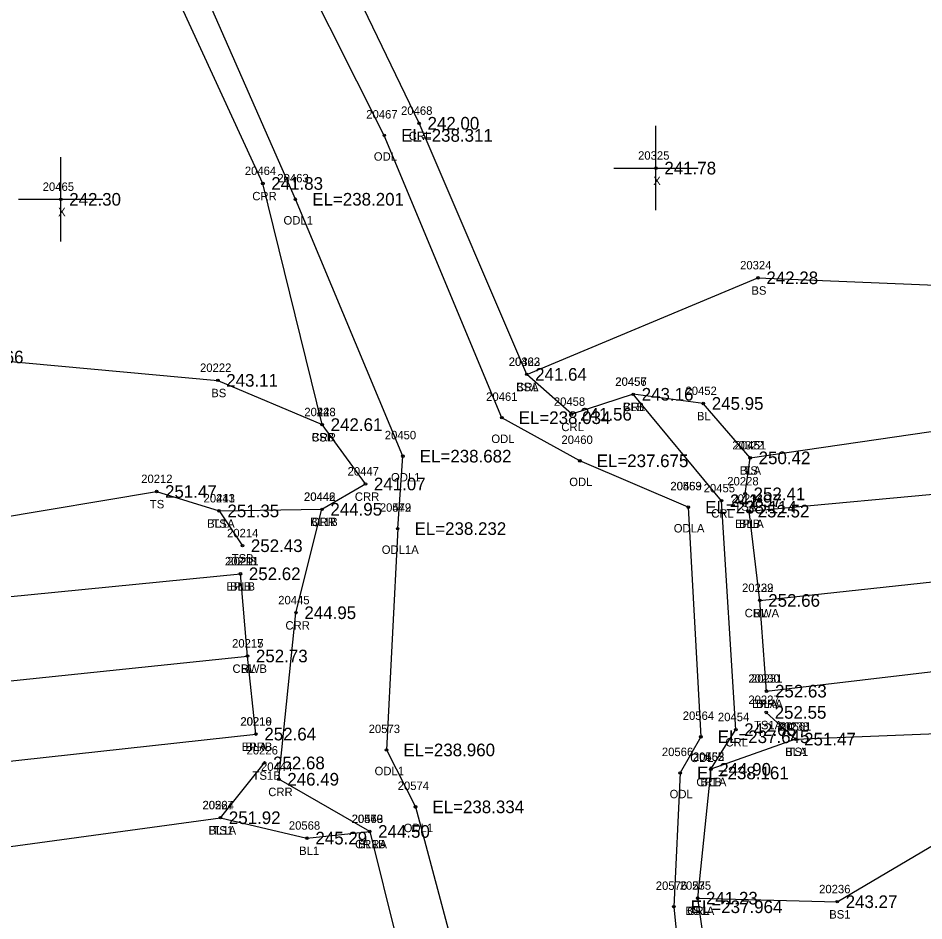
# Model space of a CAD drawing. Extents: x 2275563 to 2277161, y 1075719 to 1076412.
# Drawn here: x 2276292.5 to 2276399.9, y 1076035.8 to 1076142.9 of the extents above; entities that cross this region are included whole.
import ezdxf

# ---------------------------------------------------------------- set-up
doc = ezdxf.new("R2010")
doc.units = 0
for name, color, linetype in [('RD_DTM_BkLn1', 7, 'Continuous'), ('RD_DTM_BkLn2', 7, 'Continuous'), ('RD_DTM_BkLn_txCode', 7, 'Continuous'), ('RD_EX_H2O', 7, 'Continuous'), ('RD_EX_H2O_txCode', 7, 'Continuous'), ('RD_EX_Misc', 7, 'Continuous'), ('RD_EX_Misc_txCode', 7, 'Continuous'), ('RD_EX_Road', 7, 'Continuous'), ('RD_EX_Road_txCode', 7, 'Continuous'), ('RD_EX_TX_H2O_ELEV', 7, 'Continuous'), ('RD_EX_TX_Misc_ELEV', 7, 'Continuous'), ('RD_EX_TX_Road_ELEV', 7, 'Continuous'), ('RD_HC_Survey_ELEV', 7, 'Continuous'), ('RD_HC_Survey_txCode', 7, 'Continuous'), ('RD_SMD_Locator', 7, 'Continuous')]:
    doc.layers.add(name, color=color, linetype=linetype)

msp = doc.modelspace()

# ---------------------------------------------------------------- linework, layer by layer
at = {"layer": 'RD_DTM_BkLn1'}
for p, q in [((2276316.33, 1076084.42), (2276328.54, 1076084.61)), ((2276384.72, 1076057.35), (2276374.66, 1076053.77))]:
    msp.add_line(p, q, dxfattribs=at)
for points in [[(2276380.47, 1076073.8), (2276432.36, 1076079.4), (2276487.41, 1076086.42), (2276535.62, 1076093.32), (2276578.15, 1076099.97), (2276622.03, 1076107.93), (2276668.51, 1076117.27), (2276714.2, 1076127.81), (2276762.94, 1076140.11), (2276806.88, 1076151.96), (2276854.94, 1076166.29), (2276899.73, 1076180.7), (2276952.88, 1076198.57), (2277000.46, 1076214.72), (2277057.1, 1076234.01), (2277134.93, 1076261.07)], [(2276379.33, 1076090.71), (2276373.77, 1076097.16), (2276365.46, 1076098.25)], [(2276381.27, 1076063.04), (2276380.47, 1076073.8), (2276379.21, 1076084.39)], [(2276320.71, 1076057.95), (2276319.71, 1076067.21), (2276318.87, 1076076.96)], [(2275581.11, 1075960.98), (2275628.56, 1075975.85), (2275676.42, 1075988.42), (2275723.3, 1075998.64), (2275773.11, 1076007.87), (2275820.75, 1076014.85), (2275866.6, 1076020.4), (2275966.91, 1076031.19), (2276055.16, 1076040.4), (2276149.88, 1076050.18), (2276235.38, 1076058.41), (2276319.71, 1076067.21)], [(2276316.5, 1076048.03), (2276326.76, 1076045.61), (2276334.2, 1076046.4)]]:
    msp.add_lwpolyline(points, dxfattribs=at)
at = {"layer": 'RD_DTM_BkLn2'}
for points in [[(2276352.82, 1076100.61), (2276380.25, 1076112.06), (2276428.17, 1076110.1), (2276479.59, 1076123.58), (2276530.51, 1076128.25), (2276572.26, 1076136.92), (2276616.95, 1076145.31), (2276657.47, 1076152.34)], [(2276378.73, 1076086.44), (2276379.33, 1076090.71), (2276430.69, 1076098.18), (2276485.24, 1076104.54), (2276534.86, 1076111.23), (2276576.67, 1076117.6), (2276619.01, 1076127.99), (2276664.32, 1076137.81), (2276675.37, 1076140.15)], [(2275996.63, 1076057.66), (2276055.36, 1076067.63), (2276157.86, 1076085.08), (2276161.29, 1076085.91), (2276230.76, 1076096.53), (2276259.06, 1076089.7), (2276286.01, 1076102.67), (2276316.19, 1076099.9), (2276328.57, 1076094.65)], [(2276381.23, 1076060.52), (2276384.72, 1076057.35), (2276432.14, 1076059.24), (2276489.29, 1076068.7), (2276538.36, 1076076.43), (2276580.68, 1076083.56), (2276626.16, 1076090.05), (2276659.02, 1076095.85)], [(2276005.18, 1076050.59), (2276054, 1076055.99), (2276147.58, 1076070.47), (2276233.91, 1076079.18), (2276270.23, 1076080.23), (2276308.93, 1076086.72), (2276316.33, 1076084.42), (2276319.11, 1076080.29)], [(2276373.09, 1076038.49), (2276389.65, 1076038.07), (2276402.95, 1076045.94), (2276434.46, 1076042.78), (2276488.57, 1076051.06), (2276535.54, 1076055.99), (2276577.32, 1076064.99)], [(2276110, 1076025.4), (2276151.71, 1076032.16), (2276238.86, 1076037.41), (2276316.5, 1076048.03), (2276321.74, 1076054.53)]]:
    msp.add_lwpolyline(points, dxfattribs=at)
at = {"layer": 'RD_EX_H2O'}
for points in [[(2276371.99, 1076084.86), (2276359.12, 1076090.36), (2276349.87, 1076095.47), (2276335.93, 1076128.95), (2276310.08, 1076180.39), (2276310.66, 1076200.13), (2276321.83, 1076198.34), (2276333.62, 1076185.76), (2276354.83, 1076182.14), (2276364.71, 1076198.02), (2276372.09, 1076234.22), (2276380.37, 1076246.34), (2276391.97, 1076247.22), (2276452.13, 1076223.15), (2276471.36, 1076222.63), (2276478.94, 1076232.98), (2276472.33, 1076282.9), (2276448.49, 1076309.21), (2276451.67, 1076322.37), (2276482.4, 1076359.1), (2276495.19, 1076406.32)], [(2276374.66, 1076053.77), (2276377.62, 1076058.48), (2276375.93, 1076085.62), (2276365.46, 1076098.25), (2276358.16, 1076095.88), (2276352.82, 1076100.61), (2276340.06, 1076130.39), (2276314.72, 1076182.94), (2276314.31, 1076195.95), (2276321.34, 1076195.98), (2276333.33, 1076184.02), (2276355.21, 1076176.64), (2276375.26, 1076196.07), (2276380, 1076232.36), (2276383.62, 1076239.24), (2276390.64, 1076244.46), (2276451.84, 1076220.12), (2276472.79, 1076219.91), (2276480.77, 1076232.08), (2276477.11, 1076285.34), (2276453.42, 1076310.35), (2276458.35, 1076317.97), (2276489.24, 1076360.6), (2276498.15, 1076406.79)], [(2276337.52, 1076082.32), (2276338.14, 1076090.91), (2276325.39, 1076121.38), (2276301.23, 1076176.38), (2276301.47, 1076212.03), (2276303.94, 1076212.33), (2276322.96, 1076208.7), (2276333.72, 1076197.42), (2276353.59, 1076194.54), (2276358.22, 1076208.33), (2276360.94, 1076233.4), (2276370.36, 1076250.64), (2276386.18, 1076258.85), (2276454.86, 1076231.51), (2276469.16, 1076242), (2276461.94, 1076274.88), (2276441.6, 1076298.83), (2276443.32, 1076327.87), (2276470.76, 1076362.4), (2276481.62, 1076405.55)], [(2276334.2, 1076046.4), (2276323.43, 1076052.59), (2276325.46, 1076072.34), (2276328.54, 1076084.61), (2276333.7, 1076087.61), (2276328.57, 1076094.65), (2276321.53, 1076123.25), (2276297.42, 1076175.68), (2276298.22, 1076215.44)], [(2276371.99, 1076084.86), (2276373.47, 1076057.63), (2276371.02, 1076053.34), (2276370.27, 1076037.47), (2276373.78, 1076001.78), (2276377.12, 1075939.07), (2276387.12, 1075924.65), (2276409.24, 1075914.33), (2276440.66, 1075900.23), (2276458.72, 1075909.41), (2276468.75, 1075909.62), (2276481.14, 1075898.88), (2276470.97, 1075847.84), (2276468.69, 1075801.1), (2276495.71, 1075755.91), (2276526.48, 1075747.54)], [(2276337.52, 1076082.32), (2276336.19, 1076056.07), (2276339.64, 1076049.32), (2276347.49, 1076019.86), (2276346.94, 1075980.53), (2276334.04, 1075961.68), (2276358.91, 1075924.16), (2276390.72, 1075889.91), (2276404.64, 1075906.32), (2276409.35, 1075902.87), (2276425.82, 1075890.52), (2276463.29, 1075896.33), (2276470.94, 1075887.1), (2276454.43, 1075853.34), (2276454.95, 1075812.59), (2276477.48, 1075753.76), (2276516.05, 1075739.78)], [(2276374.66, 1076053.77), (2276373.09, 1076038.49), (2276378.35, 1076001.85), (2276379.41, 1075939.56), (2276393.18, 1075928.69), (2276410.52, 1075916.05), (2276439.66, 1075905.97), (2276458.4, 1075912.38), (2276470.74, 1075911.86), (2276484.27, 1075900.43), (2276472.97, 1075846.67), (2276473.8, 1075804.25), (2276499.15, 1075757.95), (2276529.69, 1075749.92)], [(2276334.2, 1076046.4), (2276337.42, 1076033.52), (2276345.85, 1076017.42), (2276339.02, 1075984.54), (2276329.97, 1075967.39)]]:
    msp.add_lwpolyline(points, dxfattribs=at)
at = {"layer": 'RD_EX_Misc'}
for p, q in [((2276368.15, 1076120.07), (2276368.15, 1076130.07)), ((2276297.57, 1076116.37), (2276297.57, 1076126.37)), ((2276363.15, 1076125.07), (2276373.15, 1076125.07)), ((2276292.57, 1076121.37), (2276302.57, 1076121.37))]:
    msp.add_line(p, q, dxfattribs=at)
at = {"layer": 'RD_EX_Road'}
for points in [[(2276379.21, 1076084.39), (2276432.25, 1076089.28), (2276486.22, 1076095.98), (2276535.61, 1076103.32), (2276577.16, 1076110.11), (2276620.86, 1076117.78), (2276666.21, 1076126.9), (2276712, 1076137.22), (2276761.13, 1076149.72), (2276804.56, 1076161.71), (2276851.24, 1076175.53), (2276896.93, 1076190.53), (2276950.19, 1076208.22), (2276997.45, 1076224.3), (2277053.81, 1076243.77), (2277132.14, 1076270.77)], [(2276381.27, 1076063.04), (2276433.15, 1076069.16), (2276488.59, 1076076.23), (2276537.45, 1076083.34), (2276579.64, 1076090.09), (2276624.07, 1076098.24), (2276670.54, 1076107.46), (2276716.67, 1076118.09), (2276765.18, 1076130.28), (2276809.58, 1076142.25), (2276856.93, 1076156.58), (2276903.53, 1076171.63), (2276957.27, 1076189.46), (2277005.85, 1076206.01), (2277060.98, 1076225.07), (2277139.5, 1076252.36)], [(2275577.73, 1075970.55), (2275625.95, 1075985.49), (2275674.01, 1075998.04), (2275722.5, 1076008.98), (2275771.65, 1076017.82), (2275820.48, 1076025.1), (2275865.7, 1076030.61), (2275949.17, 1076039.36), (2275965.19, 1076041.07), (2276054.28, 1076050.49), (2276149.42, 1076060.39), (2276235.13, 1076068.68), (2276318.87, 1076076.96)], [(2275583.24, 1075951.04), (2275629.66, 1075965.93), (2275678.06, 1075978.68), (2275725.56, 1075989.06), (2275775.66, 1075998.23), (2275820.79, 1076005.15), (2275867.87, 1076010.76), (2275970.82, 1076021.78), (2276056.64, 1076030.61), (2276150.8, 1076040.39), (2276237.04, 1076048.76), (2276320.71, 1076057.95)]]:
    msp.add_lwpolyline(points, dxfattribs=at)
at = {"layer": 'RD_SMD_Locator'}
for centre in [(2276340.06, 1076130.39), (2276335.93, 1076128.95), (2276368.15, 1076125.07), (2276321.53, 1076123.25), (2276297.57, 1076121.37), (2276325.39, 1076121.38), (2276380.25, 1076112.06), (2276316.19, 1076099.9), (2276352.82, 1076100.61), (2276352.82, 1076100.61), (2276365.46, 1076098.25), (2276365.46, 1076098.25), (2276373.77, 1076097.16), (2276349.87, 1076095.47), (2276358.16, 1076095.88), (2276328.57, 1076094.65), (2276328.57, 1076094.65), (2276338.14, 1076090.91), (2276359.12, 1076090.36), (2276379.33, 1076090.71), (2276379.33, 1076090.71), (2276308.93, 1076086.72), (2276333.7, 1076087.61), (2276375.93, 1076085.62), (2276378.73, 1076086.44), (2276328.54, 1076084.61), (2276328.54, 1076084.61), (2276371.99, 1076084.86), (2276371.99, 1076084.86), (2276316.33, 1076084.42), (2276316.33, 1076084.42), (2276379.21, 1076084.39), (2276379.21, 1076084.39), (2276337.52, 1076082.32), (2276337.52, 1076082.32), (2276319.11, 1076080.29), (2276318.87, 1076076.96), (2276318.87, 1076076.96), (2276380.47, 1076073.8), (2276380.47, 1076073.8), (2276325.46, 1076072.34), (2276319.71, 1076067.21), (2276319.71, 1076067.21), (2276381.27, 1076063.04), (2276381.27, 1076063.04), (2276381.23, 1076060.52), (2276320.71, 1076057.95), (2276320.71, 1076057.95), (2276377.62, 1076058.48), (2276373.47, 1076057.63), (2276384.72, 1076057.35), (2276384.72, 1076057.35), (2276336.19, 1076056.07), (2276321.74, 1076054.53), (2276374.66, 1076053.77), (2276374.66, 1076053.77), (2276374.66, 1076053.77), (2276323.43, 1076052.59), (2276371.02, 1076053.34), (2276339.64, 1076049.32), (2276316.5, 1076048.03), (2276316.5, 1076048.03), (2276334.2, 1076046.4), (2276334.2, 1076046.4), (2276334.2, 1076046.4), (2276326.76, 1076045.61), (2276373.09, 1076038.49), (2276373.09, 1076038.49), (2276370.27, 1076037.47), (2276389.65, 1076038.07)]:
    msp.add_circle(centre, 0.15, dxfattribs=at)

# ---------------------------------------------------------------- texts
at = {"layer": 'RD_DTM_BkLn_txCode'}
for s, p in [('20324', (2276378.13, 1076113.06)), ('BS', (2276379.47, 1076110.06)), ('20222', (2276314.08, 1076100.9)), ('20323', (2276350.7, 1076101.61)), ('20457', (2276363.34, 1076099.25)), ('BS', (2276315.41, 1076097.9)), ('BSA', (2276351.55, 1076098.61)), ('20452', (2276371.65, 1076098.16)), ('20223', (2276326.45, 1076095.65)), ('BLB', (2276364.23, 1076096.25)), ('BL', (2276373.01, 1076095.16)), ('BSB', (2276327.31, 1076092.65)), ('20322', (2276377.21, 1076091.71)), ('20451', (2276377.49, 1076091.71)), ('BLA', (2276378.09, 1076088.71)), ('TS', (2276378.53, 1076088.71)), ('20212', (2276307.1, 1076087.72)), ('20228', (2276376.61, 1076087.44)), ('20213', (2276314.5, 1076085.42)), ('20441', (2276314.5, 1076085.42)), ('20442', (2276326.42, 1076085.61)), ('20233', (2276377.1, 1076085.39)), ('TS', (2276308.13, 1076084.72)), ('TSA', (2276377.45, 1076084.44)), ('BL1B', (2276327.14, 1076082.61)), ('BL1A', (2276314.92, 1076082.42)), ('TS', (2276315.54, 1076082.42)), ('BLB', (2276377.99, 1076082.39)), ('20214', (2276317.28, 1076081.29)), ('TSB', (2276317.84, 1076078.29)), ('20218', (2276317.03, 1076077.96)), ('BLB', (2276317.64, 1076074.96)), ('20232', (2276378.36, 1076074.8)), ('BL', (2276379.72, 1076071.8)), ('20217', (2276317.88, 1076068.21)), ('BL', (2276318.96, 1076065.21)), ('20231', (2276379.43, 1076064.04)), ('20227', (2276379.11, 1076061.52)), ('BLA', (2276380.02, 1076061.04)), ('20216', (2276318.85, 1076058.95)), ('TS1A', (2276379.78, 1076058.52)), ('20238', (2276382.6, 1076058.35)), ('20561', (2276382.86, 1076058.35)), ('BLA', (2276319.47, 1076055.95)), ('20226', (2276319.6, 1076055.53)), ('20562', (2276372.52, 1076054.77)), ('BLA', (2276383.48, 1076055.35)), ('TS1', (2276383.76, 1076055.35)), ('TS1B', (2276320.31, 1076052.53)), ('BLB', (2276373.43, 1076051.77)), ('20567', (2276314.36, 1076049.03)), ('20224', (2276314.38, 1076049.03)), ('20569', (2276332.06, 1076047.4)), ('20568', (2276324.61, 1076046.61)), ('BL1A', (2276315.09, 1076046.03)), ('TS1', (2276315.54, 1076046.03)), ('BL1B', (2276332.81, 1076044.4)), ('BL1', (2276325.83, 1076043.61)), ('20235', (2276370.97, 1076039.49)), ('20236', (2276387.5, 1076039.07)), ('BS1A', (2276371.65, 1076036.49)), ('BS1', (2276388.7, 1076036.07))]:
    msp.add_text(s, height=1, dxfattribs=at).set_placement(p)
at = {"layer": 'RD_EX_H2O_txCode'}
for s, p in [('20467', (2276333.79, 1076130.95)), ('20468', (2276337.92, 1076131.39)), ('CRL', (2276338.83, 1076128.39)), ('ODL', (2276334.69, 1076125.95)), ('20464', (2276319.39, 1076124.25)), ('20463', (2276323.25, 1076123.38)), ('CRR', (2276320.28, 1076121.25)), ('ODL1', (2276323.98, 1076118.38)), ('20462', (2276350.68, 1076101.61)), ('20456', (2276363.32, 1076099.25)), ('CRL', (2276351.59, 1076098.61)), ('20461', (2276348.01, 1076097.47)), ('20458', (2276356.04, 1076096.88)), ('20448', (2276326.45, 1076095.65)), ('CRL', (2276364.23, 1076096.25)), ('CRL', (2276356.93, 1076093.88)), ('CRR', (2276327.31, 1076092.65)), ('20450', (2276335.99, 1076092.91)), ('ODL', (2276348.63, 1076092.47)), ('20460', (2276356.94, 1076092.36)), ('20447', (2276331.58, 1076088.61)), ('ODL1', (2276336.73, 1076087.91)), ('ODL', (2276357.87, 1076087.36)), ('20563', (2276369.85, 1076086.86)), ('20459', (2276369.87, 1076086.86)), ('20455', (2276373.81, 1076086.62)), ('20446', (2276326.4, 1076085.61)), ('CRR', (2276332.44, 1076085.61)), ('20449', (2276335.4, 1076084.32)), ('20572', (2276335.4, 1076084.32)), ('CRR', (2276327.29, 1076082.61)), ('CRL', (2276374.7, 1076083.62)), ('ODLA', (2276370.26, 1076081.86)), ('ODLA', (2276370.26, 1076081.86)), ('ODL1A', (2276335.63, 1076079.32)), ('ODL1A', (2276335.63, 1076079.32)), ('20445', (2276323.35, 1076073.34)), ('CRR', (2276324.21, 1076070.34)), ('20564', (2276371.33, 1076059.63)), ('20454', (2276375.5, 1076059.48)), ('20573', (2276334.08, 1076058.07)), ('CRL', (2276376.39, 1076056.48)), ('20566', (2276368.85, 1076055.34)), ('20565', (2276372.52, 1076054.77)), ('20453', (2276372.54, 1076054.77)), ('20444', (2276321.31, 1076053.59)), ('ODL', (2276372.22, 1076054.63)), ('ODL1', (2276334.78, 1076053.07)), ('CRLA', (2276372.94, 1076051.77)), ('CRLA', (2276372.94, 1076051.77)), ('CRR', (2276322.17, 1076050.59)), ('20574', (2276337.52, 1076051.32)), ('ODL', (2276369.77, 1076050.34)), ('20570', (2276332.05, 1076047.4)), ('20443', (2276332.08, 1076047.4)), ('ODL1', (2276338.23, 1076046.32)), ('CRRA', (2276332.46, 1076044.4)), ('CRRA', (2276332.46, 1076044.4)), ('20576', (2276368.13, 1076039.47)), ('20575', (2276370.97, 1076039.49)), ('CRL', (2276371.86, 1076036.49))]:
    msp.add_text(s, height=1, dxfattribs=at).set_placement(p)
at = {"layer": 'RD_EX_Misc_txCode'}
for s, p in [('20325', (2276366.03, 1076126.07)), ('20465', (2276295.42, 1076122.37)), ('X', (2276367.83, 1076123.07)), ('X', (2276297.25, 1076119.37))]:
    msp.add_text(s, height=1, dxfattribs=at).set_placement(p)
at = {"layer": 'RD_EX_Road_txCode'}
for s, p in [('20234', (2276377.1, 1076085.39)), ('EPLA', (2276377.52, 1076082.39)), ('20211', (2276317.32, 1076077.96)), ('EPLB', (2276317.19, 1076074.96)), ('20230', (2276379.11, 1076064.04)), ('EPRA', (2276379.55, 1076061.04)), ('20219', (2276318.88, 1076058.95)), ('EPRB', (2276319.01, 1076055.95))]:
    msp.add_text(s, height=1, dxfattribs=at).set_placement(p)
at = {"layer": 'RD_EX_TX_H2O_ELEV'}
for s, p in [('242.00', (2276341.06, 1076129.64)), ('EL=238.311', (2276337.93, 1076128.2)), ('241.83', (2276322.53, 1076122.5)), ('EL=238.201', (2276327.39, 1076120.63)), ('241.64', (2276353.82, 1076099.86)), ('243.16', (2276366.46, 1076097.5)), ('241.56', (2276359.16, 1076095.13)), ('242.61', (2276329.57, 1076093.9)), ('EL=238.034', (2276351.87, 1076094.72)), ('EL=238.682', (2276340.14, 1076090.16)), ('EL=237.675', (2276361.12, 1076089.61)), ('241.07', (2276334.7, 1076086.86)), ('241.97', (2276376.93, 1076084.87)), ('244.95', (2276329.54, 1076083.86)), ('EL=238.114', (2276373.99, 1076084.11)), ('EL=238.114', (2276373.99, 1076084.11)), ('EL=238.232', (2276339.52, 1076081.57)), ('EL=238.232', (2276339.52, 1076081.57)), ('244.95', (2276326.46, 1076071.59)), ('242.65', (2276378.62, 1076057.73)), ('EL=237.645', (2276375.47, 1076056.88)), ('EL=238.960', (2276338.19, 1076055.32)), ('EL=238.161', (2276373.02, 1076052.59)), ('244.90', (2276375.66, 1076053.02)), ('244.90', (2276375.66, 1076053.02)), ('246.49', (2276324.43, 1076051.84)), ('EL=238.334', (2276341.64, 1076048.57)), ('244.50', (2276335.2, 1076045.65)), ('244.50', (2276335.2, 1076045.65)), ('241.23', (2276374.09, 1076037.74)), ('EL=237.964', (2276372.27, 1076036.72))]:
    msp.add_text(s, height=1.5, dxfattribs=at).set_placement(p)
at = {"layer": 'RD_EX_TX_Misc_ELEV'}
for s, p in [('241.78', (2276369.15, 1076124.32)), ('242.30', (2276298.57, 1076120.62)), ('242.28', (2276381.25, 1076111.31)), ('243.66', (2276287.01, 1076101.92)), ('241.64', (2276353.82, 1076099.86)), ('243.11', (2276317.19, 1076099.15)), ('243.16', (2276366.46, 1076097.5)), ('245.95', (2276374.77, 1076096.41)), ('242.61', (2276329.57, 1076093.9)), ('250.42', (2276380.33, 1076089.96)), ('250.42', (2276380.33, 1076089.96)), ('251.47', (2276309.93, 1076085.97)), ('252.41', (2276379.73, 1076085.69)), ('251.35', (2276317.33, 1076083.67)), ('251.35', (2276317.33, 1076083.67)), ('244.95', (2276329.54, 1076083.86)), ('252.52', (2276380.21, 1076083.64)), ('252.43', (2276320.11, 1076079.54)), ('252.62', (2276319.87, 1076076.21)), ('252.66', (2276381.47, 1076073.05)), ('252.73', (2276320.71, 1076066.46)), ('252.63', (2276382.27, 1076062.29)), ('252.55', (2276382.23, 1076059.77)), ('252.64', (2276321.71, 1076057.2)), ('251.47', (2276385.72, 1076056.6)), ('251.47', (2276385.72, 1076056.6)), ('252.68', (2276322.74, 1076053.78)), ('244.90', (2276375.66, 1076053.02)), ('251.92', (2276317.5, 1076047.28)), ('251.92', (2276317.5, 1076047.28)), ('244.50', (2276335.2, 1076045.65)), ('245.29', (2276327.76, 1076044.86)), ('241.23', (2276374.09, 1076037.74)), ('243.27', (2276390.65, 1076037.32))]:
    msp.add_text(s, height=1.5, dxfattribs=at).set_placement(p)
at = {"layer": 'RD_EX_TX_Road_ELEV'}
for s, p in [('252.52', (2276380.21, 1076083.64)), ('252.62', (2276319.87, 1076076.21)), ('252.63', (2276382.27, 1076062.29)), ('252.64', (2276321.71, 1076057.2))]:
    msp.add_text(s, height=1.5, dxfattribs=at).set_placement(p)
at = {"layer": 'RD_HC_Survey_ELEV'}
for s, p in [('252.66', (2276381.47, 1076073.05)), ('252.73', (2276320.71, 1076066.46))]:
    msp.add_text(s, height=1.5, dxfattribs=at).set_placement(p)
at = {"layer": 'RD_HC_Survey_txCode'}
for s, p in [('20229', (2276378.36, 1076074.8)), ('CRWA', (2276378.67, 1076071.8)), ('20215', (2276317.88, 1076068.21)), ('CRWB', (2276317.93, 1076065.21))]:
    msp.add_text(s, height=1, dxfattribs=at).set_placement(p)

doc.saveas('drawing.dxf')
